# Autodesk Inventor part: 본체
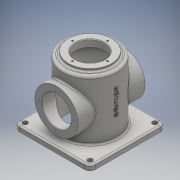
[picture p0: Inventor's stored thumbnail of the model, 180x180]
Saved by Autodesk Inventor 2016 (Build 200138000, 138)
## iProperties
Created: 2019-08
Part Number: 본체
Material: 일반
Document SubType Name: Modeling
Designer: user
Density: 1 g/cm^3
Appearance: 기본값
Author: user
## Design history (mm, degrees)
sketch "스케치1"
  geometry: L1 (60, 70)-(-60, 70); L2 (-70, 60)-(-70, -60); L3 (-60, -70)-(60, -70); L4 (70, -60)-(70, 60); L5 (70, 70)-(-70, -70); L6 (-70, 70)-(70, -70); A1 r 10 centre (-60, 60) between (-60, 70) and (-70, 60); A2 r 10 centre (-60, -60) between (-70, -60) and (-60, -70); A3 r 10 centre (60, -60) between (60, -70) and (70, -60); A4 r 10 centre (60, 60) between (70, 60) and (60, 70); 1 further point
  constraints: 12 end point, 8 point on circle, 8 point on line, 8 tangent, 4 centre point, 3 equal radius, 2 midpoint, 2 parallel, 1 horizontal, 1 perpendicular
  dimensions: "d0" = 140 distance of L5.start L6.start; "d1" = 140 distance of L6.end L5.start; "d2" = 10 radius of A1
extrude "돌출1" new body sketch "스케치1" distance "d3" = 10; taper "d4" = 0 deg
sketch "스케치2"
  geometry: C1 r 50 at (0, 0); 1 further point
  constraints: 1 centre point, 1 coincident
  dimensions: "d5" = 100 diameter of C1
extrude "돌출2" join sketch "스케치2" distance "d6" = 110; taper "d7" = 0 deg
sketch "스케치3"
  geometry: C1 r 40 at (0, 0); 1 further point
  constraints: 1 centre point, 1 coincident
  dimensions: "d8" = 80 diameter of C1
extrude "돌출3" join sketch "스케치3" distance "d9" = 5; taper "d10" = 0 deg
node "작업 평면1"
sketch "스케치4"
  geometry: L1 (-60, 0)-(60, 0) reference; C1 r 40 at (0, 60); 1 further point
  constraints: 1 centre point
  dimensions: "d12" = 80 diameter of C1; "d13" = 60 distance from line of L1 C1.centre
extrude "돌출4" join sketch "스케치4" stored distance "d14" = 5; taper "d15" = 0 deg
sketch "스케치5"
  geometry: C1 r 45 at (0, 0); 1 further point
  constraints: 1 centre point, 1 coincident
  dimensions: "d16" = 90 diameter of C1
extrude "돌출5" cut sketch "스케치5" distance "d17" = 112; taper "d18" = 0 deg
fillet "모깎기1" dims "d19" = 3
fillet "모깎기2" dims "d20" = 3
fillet "모깎기3" dims "d21" = 5
hole "구멍1" diameter "d24" = 54; stored, may be unused: countersink angle "d28" = 90 deg, drill point angle "d30" = 118 deg; dims "d22" = 10, "d23" = 10, "d25" = 6, "d26" = 4, "d27" = 2, "d29" = 8
sketch "스케치6"
  geometry: 2 further points
hole "구멍2" sketch "스케치6" at (0, 32.5) diameter "d32" = 3.242; stored, may be unused: countersink angle "d36" = 82 deg, drill point angle "d38" = 118 deg; dims "d33" = 8, "d34" = 3.023, "d35" = 2, "d37" = 10
hole "구멍3" diameter "d44" = 54; stored, may be unused: countersink angle "d48" = 82 deg, drill point angle "d50" = 0 deg; dims "d42" = 10, "d43" = 10, "d45" = 8, "d46" = 3.023, "d47" = 2, "d49" = 30
sketch "스케치7"
  geometry: 2 further points
hole "구멍4" sketch "스케치7" at (-32.5, 0) diameter "d52" = 3.242; stored, may be unused: countersink angle "d56" = 82 deg, drill point angle "d58" = 118 deg; dims "d53" = 8, "d54" = 3.023, "d55" = 2, "d57" = 10
hole "구멍5" diameter "d64" = 9; stored, may be unused: countersink angle "d68" = 82 deg, drill point angle "d70" = 0 deg; dims "d62" = 10, "d63" = 10, "d65" = 8, "d66" = 3.023, "d67" = 2, "d69" = 10
hole "구멍6" diameter "d73" = 9; stored, may be unused: countersink angle "d77" = 82 deg, drill point angle "d79" = 0 deg; dims "d71" = 10, "d72" = 10, "d74" = 8, "d75" = 3.023, "d76" = 2, "d78" = 10
chamfer "모따기1" distance "d80" = 1; stored, may be unused: second distance "d81" = 2, angle "d82" = 45 deg
fillet "모깎기4" dims "d83" = 3
fillet "모깎기5" dims "d84" = 3
fillet "모깎기6" dims "d85" = 3
node "작업 평면2"
sketch "스케치8"
  geometry: L1 (60, 0)-(-60, 0) reference; 2 further points
  constraints: 1 other
  dimensions: "d87" = 70 distance from line of L1 point (-1.996, 70)
feature "엠보싱1" sketch "스케치8" dims "d0" = 140, "d1" = 140, "d2" = 10, "d88" = 1, "d89" = 0
chamfer "모따기2" distance "d90" = 1; stored, may be unused: second distance "d91" = 2, angle "d92" = 45 deg
node "솔리드1"
mirror "대칭1"
pattern_circular "원형 패턴1" dims angle "d40" = 360 deg
mirror "대칭2"
pattern_circular "원형 패턴2" dims angle "d60" = 360 deg
mirror "대칭3"
other parameters: "d11" = -62
